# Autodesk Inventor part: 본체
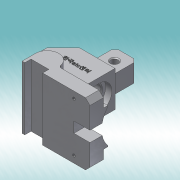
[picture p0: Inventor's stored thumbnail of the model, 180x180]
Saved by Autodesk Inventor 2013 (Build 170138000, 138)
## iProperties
Created: 2016-11
Part Number: 본체
Material: 알루미늄 6061
Document SubType Name: Modeling
Designer: dgall
Mass: 456.053 g
Surface Area: 313.578 cm^2
Volume: 168.285 cm^3
Density: 2.71 g/cm^3
Author: dgall
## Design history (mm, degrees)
sketch "스케치4"
  geometry: L1 (0, 0)-(58, 0); L2 (58, 0)-(58, 48); L3 (58, 48)-(0, 48); L4 (0, 48)-(0, 0)
  constraints: 8 end point, 2 parallel, 1 horizontal, 1 perpendicular
  dimensions: "d13" = 58 distance of L2.end L3.end; "d16" = 48 distance of L3.end L1.start
extrude "돌출3" new body sketch "스케치4" distance "d17" = 40; taper "d18" = 0 deg
node "작업 평면1"
sketch "스케치5"
  geometry: L1 (58, 48)-(18, 48) reference; L2 (58, 3)-(58, 48) reference; 2 further points
  constraints: 1 other
  dimensions: "d33" = 18 distance from line of L1 point (33, 30); "d105" = 25 distance from line of L2 point (33, 30)
sketch "스케치6"
  geometry: L1 (14, 15)-(90, 15); L2 (90, 15)-(90, -55); L3 (90, -55)-(14, -55); L4 (14, -55)-(14, 15); L5 (58, 0)-(0, 0) reference; L6 (58, -40)-(0, -40) reference; L7 (58, 0)-(58, -40) reference; L8 (58, -20)-(68.785, -20); L9 (0, 0)-(0, -40) reference
  constraints: 10 end point, 2 parallel, 2 perpendicular, 1 horizontal, 1 midpoint, 1 other
  dimensions: "d22" = 70 distance of L1.end L2.end; "d24" = 76 distance of L2.end L3.end; "d106" = 90 distance between parallel lines of L2 L9
extrude "돌출4" join sketch "스케치6" distance "d25" = 15; taper "d26" = 0 deg
sketch "스케치7"
  geometry: L1 (0, 0)-(14, 0) reference; L2 (0, 30)-(18, 48); L3 (18, 48)-(0, 48); L4 (0, 48)-(0, 30)
  constraints: 6 end point, 1 parallel, 1 perpendicular
  dimensions: "d28" = 18 distance of L2.end L3.end
extrude "돌출5" cut sketch "스케치7" stored distance "d29" = 15; taper "d30" = 0 deg
extrude "돌출6" join sketch "스케치5" distance "d31" = 0.5; taper "d32" = 0 deg
sketch "스케치8"
  geometry: L1 (-40, 40)-(-40, 0) reference; L2 (0, 0)-(-40, 0) reference; L3 (0, 40)-(0, 0) reference; L4 (0, 40)-(-40, 40) reference; L5 (0, 20)-(-68.106, 20); L6 (-5, 30)-(-30, 30); L7 (-30, 30)-(-30, 10); L8 (-30, 10)-(-5, 10); L9 (-5, 10)-(-5, 30); L10 (-58, 0)-(-58, 40) reference
  constraints: 10 end point, 3 parallel, 1 horizontal, 1 midpoint, 1 perpendicular, 1 other
  dimensions: "d36" = 20 distance of L6.end L7.end; "d38" = 25 distance of L6.start L6.end; "d40" = 53 distance between parallel lines of L9 L10
extrude "돌출7" join sketch "스케치8" distance "d41" = 30; taper "d42" = 0 deg
chamfer "모따기1" distance "d43" = 4; stored, may be unused: second distance "d44" = 2, angle "d45" = 45 deg
sketch "스케치9"
  geometry: L1 (90, -55)-(90, 15) reference; L2 (90, 0)-(90, -40); L3 (90, 0)-(0, 0); L4 (0, 0)-(0, -40); L5 (0, -40)-(90, -40)
  constraints: 8 end point, 2 perpendicular, 1 parallel, 1 point on line
  dimensions: "d46" = 40 distance of L2.start L2.end
extrude "돌출8" join sketch "스케치9" distance "d48" = 5; taper "d49" = 0 deg
chamfer "모따기2" distance "d50" = 4; stored, may be unused: second distance "d51" = 2, angle "d52" = 45 deg
sketch "스케치10"
  geometry: L1 (76, 0)-(0, 0) reference; L2 (0, 15)-(76, 15) reference; L3 (0, 0)-(0, 15) reference; L4 (3, 0)-(23, 0); L5 (23, 0)-(23, 7); L6 (23, 7)-(3, 7); L7 (3, 7)-(3, 0); 2 further points
  constraints: 8 end point, 2 parallel, 2 point on line, 1 horizontal, 1 horizontal alignment, 1 perpendicular, 2 other
  dimensions: "d53" = 3 distance between parallel lines of L3 L7; "d54" = 20 distance between parallel lines of L5 L7; "d55" = 7 distance between parallel lines of L1 L6
extrude "돌출9" join sketch "스케치10" distance "d56" = 70; taper "d57" = 0 deg
extrude "돌출10" cut sketch "스케치10" distance "d58" = 70; taper "d59" = 0 deg
sketch "스케치11"
  geometry: L1 (40, -40)-(40, 0) reference; L2 (40, 0)-(0, 0) reference; L3 (0, -40)-(0, 0) reference; L4 (0, -40)-(40, -40) reference; L5 (40, -48)-(0, -48) reference; C1 r 10 at (20, -18); C2 r 14.5 at (20, -18)
  constraints: 2 centre point, 1 coincident
  dimensions: "d60" = 29 diameter of C2; "d62" = 20 diameter of C1; "d130" = 30 distance from line of L5 C1.centre
extrude "돌출11" cut sketch "스케치11" distance "d63" = 70; taper "d64" = 0 deg
extrude "돌출12" cut sketch "스케치11" distance "d65" = 7; taper "d66" = 0 deg
sketch "스케치12"
  geometry: L1 (4, 30)-(21, 30) reference; L2 (0, 0)-(0, 26) reference; L3 (25, 0)-(25, 26) reference; L4 (62, -60)-(9, -60) reference; 2 further points
  dimensions: "d67" = 12.5 distance from line of L2 point (12.5, 17); "d68" = 77 distance from line of point (12.5, 17) L4
hole "구멍1" sketch "스케치12" at (12.5, 17) diameter "d69" = 8; stored, may be unused: countersink angle "d73" = 90 deg, drill point angle "d75" = 118 deg; dims "d70" = 6, "d71" = 4, "d72" = 2, "d74" = 8
chamfer "모따기3" distance "d76" = 1; stored, may be unused: second distance "d77" = 2, angle "d78" = 45 deg
chamfer "모따기4" distance "d79" = 1; stored, may be unused: second distance "d80" = 2, angle "d81" = 45 deg
sketch "스케치13"
  geometry: L1 (70, 0)-(0, 0) reference; L2 (70, 0)-(70, 15) reference; L3 (55, 15)-(70, 15) reference; L4 (55, 15)-(55, 20) reference; L5 (15, 20)-(55, 20) reference; L6 (15, 15)-(15, 20) reference; L7 (0, 15)-(15, 15) reference; L8 (0, 0)-(0, 15) reference; C1 r 14.5 at (35, 42) reference; C2 r 29 at (35, 42); 1 further point
  constraints: 1 centre point, 1 coincident
  dimensions: "d82" = 58 diameter of C2
extrude "돌출13" cut sketch "스케치13" distance "d84" = 18; taper "d85" = 0 deg
sketch "스케치14"
  geometry: L1 (15, 15)-(15, 20) reference; L2 (0, 15)-(15, 15) reference; L3 (0, 0)-(0, 15) reference; L4 (70, 0)-(0, 0) reference; L5 (70, 0)-(70, 15) reference; L6 (55, 15)-(70, 15) reference; L7 (55, 15)-(55, 20) reference; L8 (29, 0)-(41, 0); L9 (41, 0)-(41, 15.102); L10 (41, 15.102)-(29, 15.102); L11 (29, 15.102)-(29, 0); L12 (35, 13)-(35, -3.878); L13 (15, 20)-(16.106, 20) reference; L14 (53.894, 20)-(55, 20) reference; A1 r 29 centre (35, 42) between (16.106, 20) and (53.894, 20) reference; 1 further point
  constraints: 10 end point, 3 parallel, 1 horizontal, 1 perpendicular, 1 point on circle, 1 point on line, 1 other
  dimensions: "d87" = 12 distance between parallel lines of L9 L11
extrude "돌출14" cut sketch "스케치14" distance "d89" = 18; taper "d90" = 0 deg
sketch "스케치15"
  geometry: L1 (90, 0)-(90, 15) reference; L2 (40, 15)-(40, 0) reference; L3 (90, 0)-(40, 0) reference; L4 (90, 0)-(90, 15) reference; L5 (90, 15)-(40, 15) reference; L6 (40, -40)-(40, -55) reference; L7 (40, -55)-(90, -55) reference; L8 (90, -55)-(90, -40) reference; L9 (90, -40)-(40, -40) reference; 3 further points
  dimensions: "d91" = 18 distance from line of L8 point (72, -47.5); "d92" = 18 distance from line of L1 point (72, 7.5); "d114" = 55 distance of point (72, -47.5) point (72, 7.5)
  node "투영된 루프4"
  node "투영된 루프5"
chamfer "모따기5" distance "d100" = 5; stored, may be unused: second distance "d101" = 2, angle "d102" = 45 deg
fillet "모깎기1" dims "d103" = 3
fillet "모깎기2" dims "d104" = 3
hole "구멍4" sketch "스케치15" diameter "d123" = 3.242; stored, may be unused: countersink angle "d127" = 90 deg, drill point angle "d129" = 118 deg; dims "d124" = 6, "d125" = 4, "d126" = 2, "d128" = 8
node "솔리드3"
node "투영된 루프1"
node "투영된 루프2"
node "투영된 루프3"
